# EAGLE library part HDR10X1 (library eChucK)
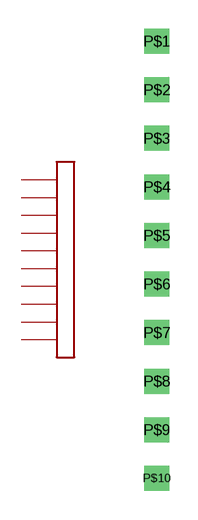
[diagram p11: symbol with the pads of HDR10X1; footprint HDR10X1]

Designator prefix H

## HDR10X1  [HDR10X1]
P$1  P$1
P$2  P$2
P$3  P$3
P$4  P$4
P$5  P$5
P$6  P$6
P$7  P$7
P$8  P$8
P$9  P$9
P$10  P$10

## Footprint HDR10X1 (pad centres in mm)
drill 0.8 square: P$1 0,11.43; P$2 0,8.89; P$3 0,6.35; P$4 0,3.81; P$5 0,1.27; P$6 0,-1.27; P$7 0,-3.81; P$8 0,-6.35; P$9 0,-8.89; P$10 0,-11.43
